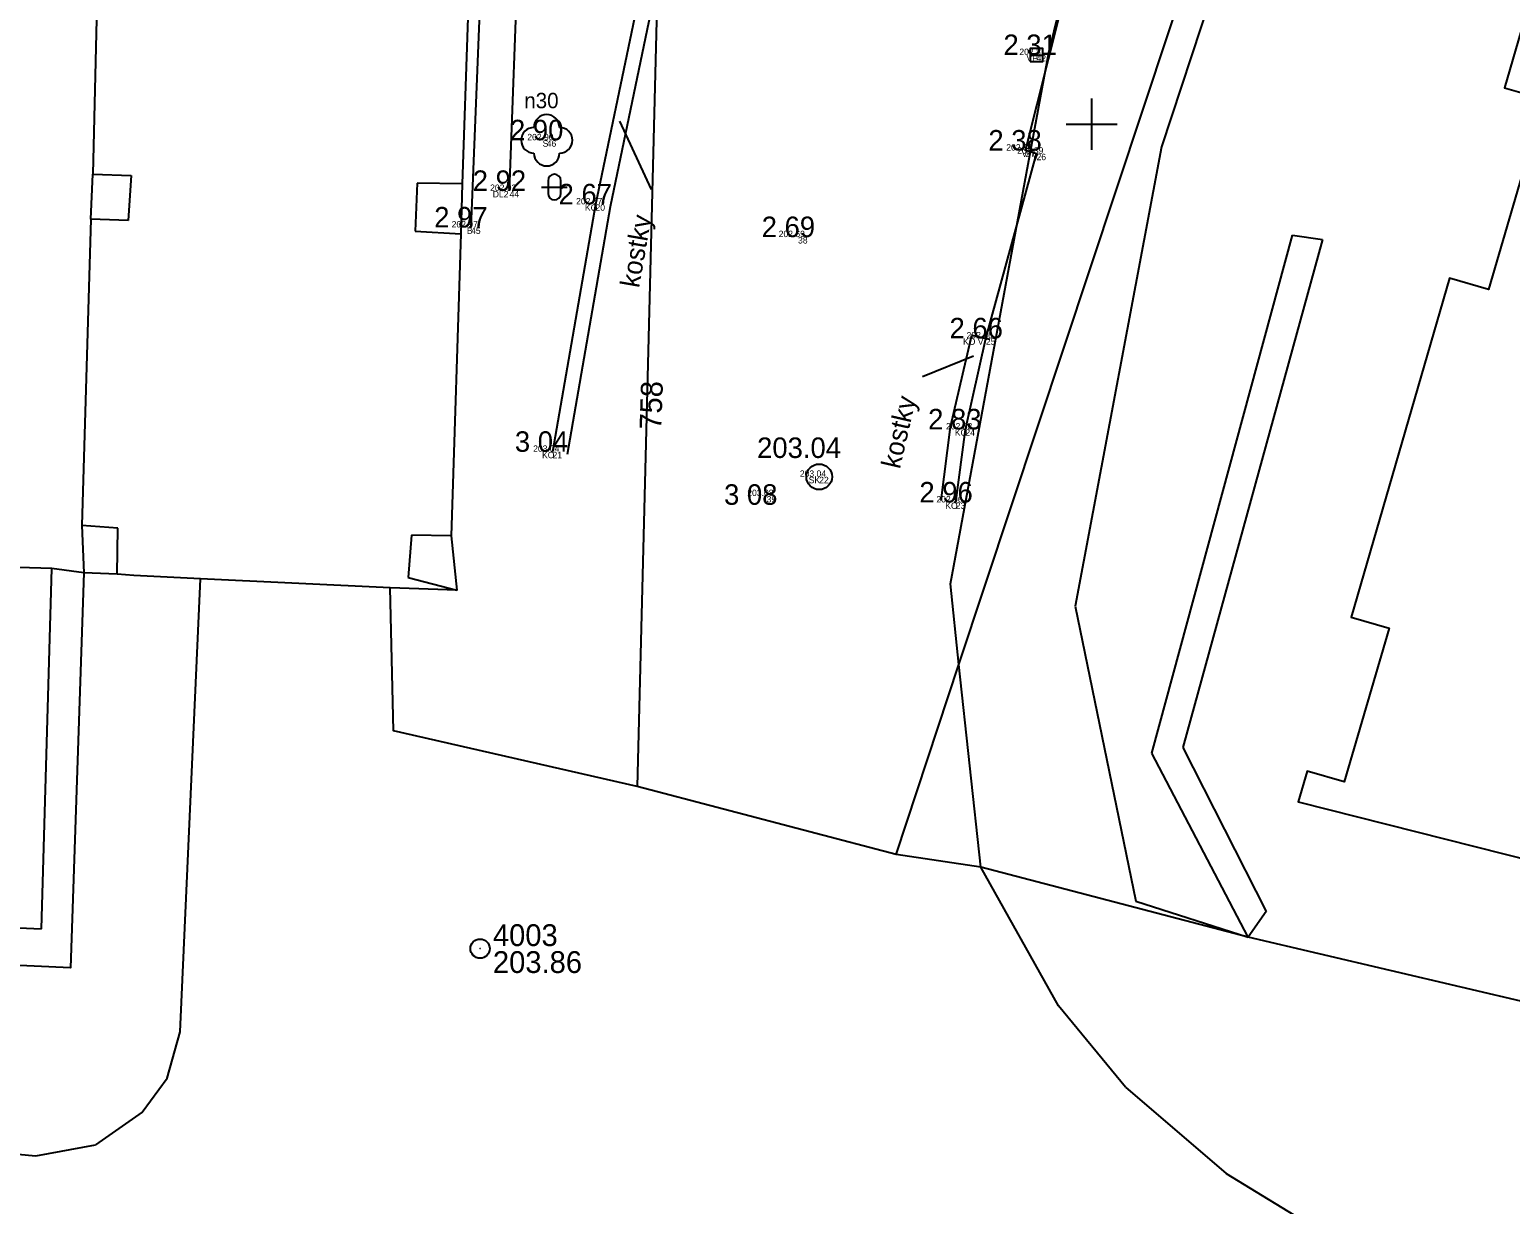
# Model space of a CAD drawing. Extents: x -599717 to -599336, y -1161826 to -1161587.
# Drawn here: x -599496.57 to -599473.47, y -1161736.85 to -1161718.52 of the extents above; entities that cross this region are included whole.
import ezdxf

# ---------------------------------------------------------------- set-up
doc = ezdxf.new("R2010")
doc.units = 0
for name, color, linetype in [('BODY', 7, 'Continuous'), ('BODY_CISLA', 7, 'Continuous'), ('BODY_KODY', 7, 'Continuous'), ('BODY_POLYGONY', 7, 'Continuous'), ('BODY_VYSKY_CELE', 7, 'Continuous'), ('G_BUDOVY', 7, 'Continuous'), ('G_POLOHOPIS', 7, 'Continuous'), ('G_TEXTY', 7, 'Continuous'), ('G_ZELEN', 7, 'Continuous'), ('G_ZNACKY', 7, 'Continuous'), ('H_KOTY_VYSKOVE', 7, 'Continuous'), ('KN_Hranice parcel', 7, 'Continuous'), ('KN_Parcelní čísla', 7, 'Continuous'), ('KN_Vnitřní kresba', 7, 'Continuous'), ('KN_Značky kultur', 7, 'Continuous'), ('X_SOUR_KRIZKY_SEVER', 7, 'Continuous')]:
    doc.layers.add(name, color=color, linetype=linetype)

msp = doc.modelspace()

# ---------------------------------------------------------------- linework, layer by layer
at = {"layer": 'BODY'}
for p, q in [((-599480.86, -1161718.92), (-599480.86, -1161718.92)), ((-599488.5, -1161720.25), (-599488.5, -1161720.25)), ((-599481.03, -1161720.41), (-599481.03, -1161720.41)), ((-599480.86, -1161720.46), (-599480.86, -1161720.46)), ((-599489.08, -1161721.04), (-599489.08, -1161721.04)), ((-599487.74, -1161721.25), (-599487.74, -1161721.25)), ((-599489.68, -1161721.61), (-599489.68, -1161721.61)), ((-599484.58, -1161721.76), (-599484.58, -1161721.76)), ((-599481.65, -1161723.34), (-599481.65, -1161723.34)), ((-599481.97, -1161724.76), (-599481.97, -1161724.76)), ((-599488.41, -1161725.11), (-599488.41, -1161725.11)), ((-599484.25, -1161725.5), (-599484.25, -1161725.5)), ((-599485.07, -1161725.8), (-599485.07, -1161725.8)), ((-599482.12, -1161725.9), (-599482.12, -1161725.9))]:
    msp.add_line(p, q, dxfattribs=at)
at = {"layer": 'BODY_POLYGONY'}
for radius in [0.15, 0.0002]:
    msp.add_circle((-599489.54, -1161732.86), radius, dxfattribs=at)
at = {"layer": 'G_BUDOVY'}
msp.add_lwpolyline([(-599489.68, -1161721.61), (-599489.5, -1161717.21), (-599490.555, -1161717.2)], dxfattribs=at)
at = {"layer": 'G_POLOHOPIS'}
for points in [[(-599489.08, -1161721.04), (-599488.94, -1161717.25), (-599488.92, -1161716.66), (-599490.9, -1161716.56)], [(-599486.81, -1161717.07), (-599487.13, -1161718.34), (-599487.74, -1161721.25), (-599488.41, -1161725.11)], [(-599486.571, -1161717.054), (-599486.91, -1161718.39), (-599487.51, -1161721.29), (-599488.18, -1161725.15)], [(-599481.65, -1161723.34), (-599480.86, -1161720.46), (-599481.03, -1161720.41), (-599480.49, -1161718.26)], [(-599482.35, -1161725.87), (-599482.2, -1161724.72), (-599481.87, -1161723.29), (-599481.596, -1161723.351)], [(-599482.12, -1161725.9), (-599481.97, -1161724.76), (-599481.65, -1161723.34)]]:
    msp.add_lwpolyline(points, dxfattribs=at)
at = {"layer": 'G_TEXTY'}
for p, q in [((-599486.864, -1161721.018), (-599487.361, -1161719.952)), ((-599482.641, -1161723.936), (-599481.845, -1161723.614))]:
    msp.add_line(p, q, dxfattribs=at)
at = {"layer": 'G_ZELEN'}
msp.add_circle((-599488.5, -1161720.25), 0.0002, dxfattribs=at)
for centre, start, end in [((-599488.5, -1161720.05), 0, 180), ((-599488.7, -1161720.25), 90, 270), ((-599488.3, -1161720.25), 270, 90), ((-599488.5, -1161720.45), 180, 360)]:
    msp.add_arc(centre, 0.2, start, end, dxfattribs=at)
at = {"layer": 'G_ZNACKY'}
msp.add_line((-599480.96, -1161718.92), (-599480.76, -1161718.92), dxfattribs=at)
msp.add_lwpolyline([(-599480.96, -1161719.02), (-599480.76, -1161719.02), (-599480.76, -1161718.82), (-599480.96, -1161718.82)], close=True, dxfattribs=at)
msp.add_circle((-599484.25, -1161725.5), 0.2, dxfattribs=at)
at = {"layer": 'KN_Hranice parcel'}
for q in [(-599482.07, -1161728.43), (-599487.09, -1161730.33)]:
    msp.add_line((-599483.05, -1161731.39), q, dxfattribs=at)
for points in [[(-599482.07, -1161728.43), (-599482.2, -1161727.17), (-599480.67, -1161718.88), (-599478.61, -1161710.51), (-599472.1, -1161690.95), (-599466.87, -1161675.9), (-599461.06, -1161668.48), (-599459.51, -1161667.19)], [(-599482.07, -1161728.43), (-599464.01, -1161674), (-599459.51, -1161667.19)], [(-599472.61, -1161674.6), (-599486.77, -1161717.76), (-599487.09, -1161730.33)], [(-599472.66, -1161716.33), (-599473.56, -1161719.43), (-599472.94, -1161719.61), (-599473.81, -1161722.58), (-599474.42, -1161722.4), (-599475.95, -1161727.69), (-599475.36, -1161727.86), (-599476.06, -1161730.26), (-599476.64, -1161730.09), (-599476.78, -1161730.57), (-599459.34, -1161734.98)], [(-599489.72, -1161717.52), (-599489.73, -1161718.34), (-599489.82, -1161720.93), (-599489.84, -1161721.71), (-599489.99, -1161726.42), (-599489.9, -1161727.27), (-599490.94, -1161727.23)], [(-599490.94, -1161727.23), (-599493.9, -1161727.09), (-599494.94, -1161727.04), (-599495.2, -1161727.02), (-599495.72, -1161727), (-599495.93, -1161733.16), (-599523.16, -1161731.91), (-599554.4, -1161731.7), (-599554.98, -1161731.73), (-599556.92, -1161731.64), (-599564.93, -1161730.47), (-599565.19, -1161736.81), (-599564.48, -1161736.87), (-599564.6, -1161737.26), (-599565.68, -1161737.31), (-599572.63, -1161739.15), (-599582.79, -1161738.54)], [(-599487.09, -1161730.33), (-599490.89, -1161729.46), (-599490.94, -1161727.23)], [(-599459.84, -1161736.84), (-599477.56, -1161732.68), (-599481.73, -1161731.59), (-599483.05, -1161731.39)]]:
    msp.add_lwpolyline(points, dxfattribs=at)
at = {"layer": 'KN_Vnitřní kresba'}
for p, q in [((-599464.97, -1161677.92), (-599478.91, -1161720.35)), ((-599495.52, -1161718.14), (-599495.58, -1161720.78)), ((-599478.91, -1161720.35), (-599480.26, -1161727.52)), ((-599495.61, -1161721.48), (-599495.58, -1161720.78)), ((-599495.58, -1161720.78), (-599494.98, -1161720.8)), ((-599494.98, -1161720.8), (-599495.03, -1161721.5)), ((-599490.52, -1161720.92), (-599490.55, -1161721.67)), ((-599489.82, -1161720.93), (-599490.52, -1161720.92)), ((-599495.61, -1161721.48), (-599495.75, -1161726.26)), ((-599495.03, -1161721.5), (-599495.61, -1161721.48)), ((-599490.55, -1161721.67), (-599489.84, -1161721.71)), ((-599479.06, -1161729.81), (-599476.87, -1161721.73)), ((-599476.87, -1161721.73), (-599476.4, -1161721.8)), ((-599476.4, -1161721.8), (-599478.58, -1161729.72)), ((-599496.22, -1161726.93), (-599523.84, -1161726.16)), ((-599495.19, -1161726.3), (-599495.75, -1161726.26)), ((-599495.75, -1161726.26), (-599495.72, -1161727)), ((-599495.2, -1161727.02), (-599495.19, -1161726.3)), ((-599490.61, -1161726.41), (-599490.66, -1161727.07)), ((-599489.99, -1161726.42), (-599490.61, -1161726.41)), ((-599496.38, -1161732.55), (-599496.22, -1161726.93)), ((-599495.72, -1161727), (-599496.22, -1161726.93)), ((-599490.66, -1161727.07), (-599489.9, -1161727.27)), ((-599494.22, -1161734.16), (-599493.9, -1161727.09)), ((-599480.26, -1161727.52), (-599479.31, -1161732.12)), ((-599481.73, -1161731.59), (-599482.07, -1161728.43)), ((-599477.56, -1161732.68), (-599479.06, -1161729.81)), ((-599478.58, -1161729.72), (-599477.28, -1161732.28)), ((-599522.92, -1161731.36), (-599496.38, -1161732.55)), ((-599480.52, -1161733.75), (-599481.73, -1161731.59)), ((-599479.31, -1161732.12), (-599477.56, -1161732.68)), ((-599477.28, -1161732.28), (-599477.56, -1161732.68)), ((-599527.42, -1161733.43), (-599496.47, -1161736.09)), ((-599479.47, -1161735.02), (-599480.52, -1161733.75)), ((-599494.42, -1161734.88), (-599494.22, -1161734.16)), ((-599494.81, -1161735.41), (-599494.42, -1161734.88)), ((-599479.47, -1161735.02), (-599477.9, -1161736.37)), ((-599494.81, -1161735.41), (-599495.54, -1161735.92)), ((-599496.47, -1161736.09), (-599495.54, -1161735.92)), ((-599477.9, -1161736.37), (-599476.47, -1161737.24))]:
    msp.add_line(p, q, dxfattribs=at)
at = {"layer": 'KN_Značky kultur'}
for p, q in [((-599488.58, -1161720.98), (-599488.18, -1161720.98)), ((-599488.48, -1161720.88), (-599488.48, -1161721.08)), ((-599488.28, -1161721.08), (-599488.28, -1161720.88))]:
    msp.add_line(p, q, dxfattribs=at)
for centre, start, end in [((-599488.38, -1161720.88), 0, 180), ((-599488.38, -1161721.08), 180, 359.9879)]:
    msp.add_arc(centre, 0.1, start, end, dxfattribs=at)
at = {"layer": 'X_SOUR_KRIZKY_SEVER'}
for p, q in [((-599480, -1161720.4), (-599480, -1161719.6)), ((-599480.4, -1161720), (-599479.6, -1161720))]:
    msp.add_line(p, q, dxfattribs=at)

# ---------------------------------------------------------------- texts
at = {"layer": 'BODY_CISLA'}
for s, p in [('42', (-599480.86, -1161719.02)), ('46', (-599488.5, -1161720.35)), ('27', (-599481.03, -1161720.51)), ('26', (-599480.86, -1161720.56)), ('44', (-599489.08, -1161721.14)), ('20', (-599487.74, -1161721.35)), ('45', (-599489.68, -1161721.71)), ('38', (-599484.58, -1161721.86)), ('25', (-599481.65, -1161723.44)), ('24', (-599481.97, -1161724.86)), ('21', (-599488.41, -1161725.21)), ('22', (-599484.25, -1161725.6)), ('39', (-599485.07, -1161725.9)), ('23', (-599482.12, -1161726))]:
    msp.add_text(s, height=0.1, dxfattribs=at).set_placement(p)
at = {"layer": 'BODY_KODY'}
for s, p in [('VP', (-599481.016, -1161719.02)), ('S', (-599488.565, -1161720.35)), ('V', (-599481.091, -1161720.51)), ('V', (-599480.921, -1161720.56)), ('DL2', (-599489.342, -1161721.14)), ('KO', (-599487.904, -1161721.35)), ('B', (-599489.745, -1161721.71)), ('KO V', (-599482.007, -1161723.44)), ('KO', (-599482.134, -1161724.86)), ('KO', (-599488.574, -1161725.21)), ('SK', (-599484.414, -1161725.6)), ('KO', (-599482.284, -1161726))]:
    msp.add_text(s, height=0.1, dxfattribs=at).set_placement(p)
at = {"layer": 'BODY_POLYGONY'}
for s, p in [('4003', (-599489.34, -1161732.82)), ('203.86', (-599489.34, -1161733.24))]:
    msp.add_text(s, height=0.34, dxfattribs=at).set_placement(p)
at = {"layer": 'BODY_VYSKY_CELE'}
for s, p in [('202.31 ', (-599481.128, -1161718.92)), ('202.90 ', (-599488.803, -1161720.25)), ('202.38 ', (-599481.332, -1161720.41)), ('202.39 ', (-599481.162, -1161720.46)), ('202.92 ', (-599489.383, -1161721.04)), ('202.67 ', (-599488.042, -1161721.25)), ('202.97 ', (-599489.983, -1161721.61)), ('202.69 ', (-599484.882, -1161721.76)), ('202.66 ', (-599481.951, -1161723.34)), ('202.83 ', (-599482.272, -1161724.76)), ('203.04 ', (-599488.712, -1161725.11)), ('203.04 ', (-599484.552, -1161725.5)), ('203.08 ', (-599485.372, -1161725.8)), ('202.96 ', (-599482.422, -1161725.9))]:
    msp.add_text(s, height=0.1, dxfattribs=at).set_placement(p)
at = {"layer": 'G_TEXTY'}
msp.add_text('n30', height=0.24, dxfattribs=at).set_placement((-599488.851, -1161719.75))
for rotation, p in [(80.153, (-599487.06, -1161722.563)), (77.0054, (-599482.993, -1161725.388))]:
    msp.add_text('kostky', height=0.3, rotation=rotation, dxfattribs=at).set_placement(p)
at = {"layer": 'H_KOTY_VYSKOVE'}
for s, p in [(' 2 31', (-599481.495, -1161718.92)), (' 2 90', (-599489.192, -1161720.25)), (' 2 38', (-599481.73, -1161720.41)), (' 2 92', (-599489.773, -1161721.04)), (' 2 67', (-599488.434, -1161721.25)), (' 2 97', (-599490.374, -1161721.61)), (' 2 69', (-599485.266, -1161721.76)), (' 2 66', (-599482.336, -1161723.34)), (' 2 83', (-599482.67, -1161724.76)), (' 3 04', (-599489.116, -1161725.11)), ('203.04 ', (-599485.219, -1161725.206)), (' 3 08', (-599485.853, -1161725.936)), (' 2 96', (-599482.806, -1161725.9))]:
    msp.add_text(s, height=0.32, dxfattribs=at).set_placement(p)
at = {"layer": 'KN_Parcelní čísla'}
msp.add_text('758', height=0.34, rotation=88, dxfattribs=at).set_placement((-599486.714, -1161724.769))

doc.saveas('drawing.dxf')
